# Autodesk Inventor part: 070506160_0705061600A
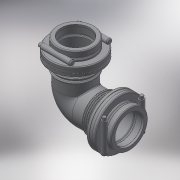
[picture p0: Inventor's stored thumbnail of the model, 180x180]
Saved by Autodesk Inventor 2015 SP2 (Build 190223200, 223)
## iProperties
Created: 2017-05
Part Number: 070506160_0705061600A
Material: Generic
Description: PLASSON 90° ELBOW 160-160
Document SubType Name: Modeling
Designer: KIM
Density: 1 g/cm^3
Appearance: Default
Author: KIM
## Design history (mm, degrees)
derived "070506.ipt"
feature "Solid1::070506.ipt"
tag "TaggingFeature1"
body "Solid1"
other parameters: "d0" = 301, "d3" = 208, "d4" = 192, "d5" = 4.8, "d6" = 51, "d7" = 274.4, "d9" = 204, "d10" = 51, "d11" = 9.6, "d12" = 51, "d13" = 10.2, "d15" = 4.8, "d17" = 161.6, "d18" = 11.55, "d19" = 0, "d21" = 0, "d23" = 20.16, "d24" = 16, "d25" = 0, "d26" = 1.6, "d29" = 0.1, "d30" = 8, "d31" = 0, "d32" = 4.8, "d33" = 144, "d34" = 224.4, "d36" = 90 deg, "d38" = 90 deg, "d39" = 5, "l_" = 204, "A_" = 301, "d16" = 46.2, "d22" = 28.8
